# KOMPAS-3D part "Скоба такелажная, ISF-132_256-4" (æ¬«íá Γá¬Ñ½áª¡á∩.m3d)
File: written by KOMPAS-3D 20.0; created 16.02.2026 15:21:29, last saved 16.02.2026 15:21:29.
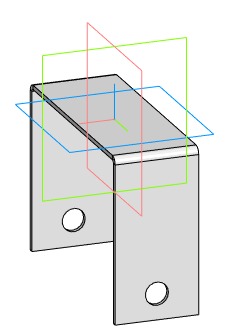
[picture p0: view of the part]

Document properties: Автор: admin; Полное имя файла: P:\INSTART\Технический отдел\ОР\Прочие задачи\КД на номенклатурный ряд\КД на типоразмеры дросселей\Сетевые дроссели ISF\ISF-4\Тип 1\ISF-132_256-4\0723\Новая папка\Скоба такелажная.m3d

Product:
- Part/product: Скоба такелажная  | designation ISF-132_256-4

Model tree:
1. Операция без истории:1

Expressions: ISF-132_256-4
